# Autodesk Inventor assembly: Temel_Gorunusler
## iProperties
Shininess: 64.0
Length Units: 11269
Angle Units: 11279
Time Units: 11290
Mass Units: 11283
Length Display Precision: 3
Angle Display Precision: 2
Compacted: True
Created: 2004-01
Part Number: Temel_Gorunusler
Document SubType Name: Assembly
Designer: Administrator
Manufacturer: Standard
Standards Organization: Custom
Density: 0.0
Volumn: 0.0
Area: 0.0
PropertySet Name: Model Information
Control State: 0
Master: False
Checked Out: False
Author: Administrator
